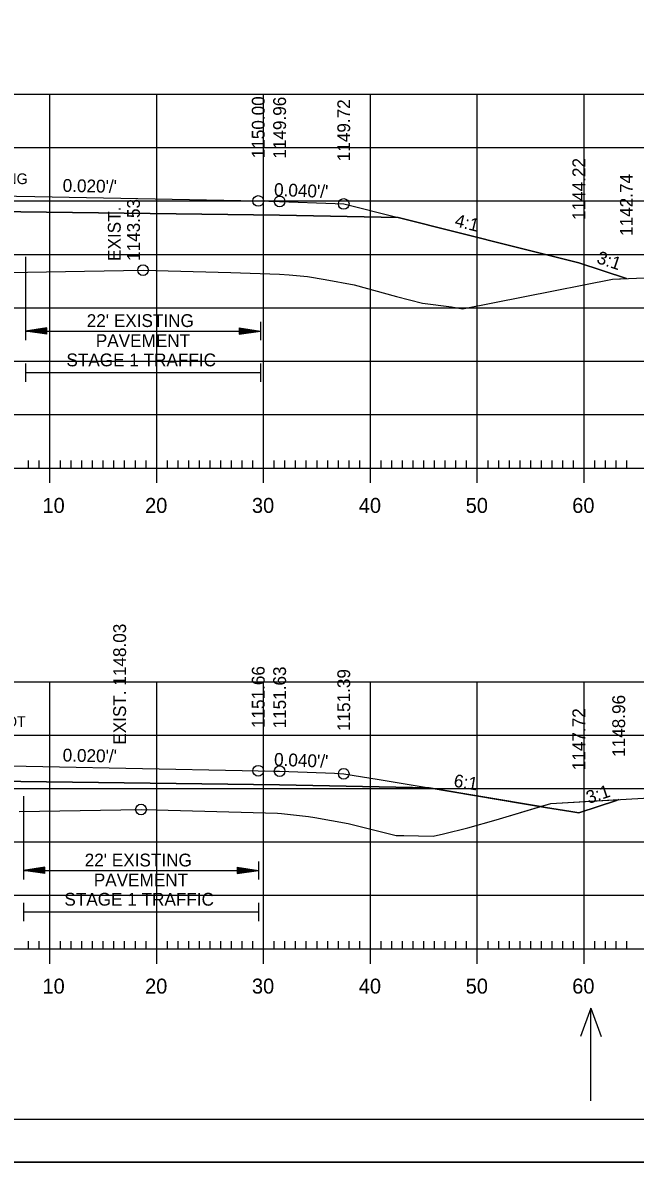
# Model space of a CAD drawing. Extents: x 1322838 to 1324533, y 339903 to 351025.
# Drawn here: x 1323711.2 to 1323768.5, y 341609.8 to 341716.5 of the extents above; entities that cross this region are included whole.
import ezdxf

# ---------------------------------------------------------------- set-up
doc = ezdxf.new("R2010")
doc.units = 0
for name, color, linetype in [('R_Alt Surface', 7, 'Continuous'), ('R_Axis', 7, 'Continuous'), ('R_Axis Annot', 7, 'Continuous'), ('R_Border', 7, 'Continuous'), ('R_Exist Surface', 7, 'Continuous'), ('R_Fin Surface', 7, 'Continuous'), ('R_Fin Surface Annot', 7, 'Continuous'), ('R_Grid', 7, 'Continuous'), ('R_No Plot', 7, 'Continuous'), ('R_Water Annot', 7, 'Continuous'), ('R_Xsect Elev', 7, 'Continuous')]:
    doc.layers.add(name, color=color, linetype=linetype)

msp = doc.modelspace()

# ---------------------------------------------------------------- linework, layer by layer
at = {"layer": 'R_Alt Surface'}
for points in [[(1323661.12, 341698.25), (1323672.22, 341698.48), (1323703.72, 341698.9), (1323735.22, 341698.48), (1323746.31, 341698.25)], [(1323661.12, 341644.92), (1323672.22, 341645.14), (1323703.72, 341645.56), (1323735.22, 341645.14), (1323749.21, 341644.86)]]:
    msp.add_lwpolyline(points, dxfattribs=at)
at = {"layer": 'R_Axis'}
for p, q in [((1323713.72, 341673.41), (1323713.72, 341676.21)), ((1323723.72, 341673.41), (1323723.72, 341676.21)), ((1323733.72, 341673.41), (1323733.72, 341676.21)), ((1323743.72, 341673.41), (1323743.72, 341676.21)), ((1323753.72, 341673.41), (1323753.72, 341676.21)), ((1323763.72, 341673.41), (1323763.72, 341676.21)), ((1323711.72, 341674.81), (1323711.72, 341675.51)), ((1323712.72, 341674.81), (1323712.72, 341675.51)), ((1323714.72, 341674.81), (1323714.72, 341675.51)), ((1323715.72, 341674.81), (1323715.72, 341675.51)), ((1323716.72, 341674.81), (1323716.72, 341675.51)), ((1323717.72, 341674.81), (1323717.72, 341675.51)), ((1323718.72, 341674.81), (1323718.72, 341675.51)), ((1323719.72, 341674.81), (1323719.72, 341675.51)), ((1323720.72, 341674.81), (1323720.72, 341675.51)), ((1323721.72, 341674.81), (1323721.72, 341675.51)), ((1323722.72, 341674.81), (1323722.72, 341675.51)), ((1323724.72, 341674.81), (1323724.72, 341675.51)), ((1323725.72, 341674.81), (1323725.72, 341675.51)), ((1323726.72, 341674.81), (1323726.72, 341675.51)), ((1323727.72, 341674.81), (1323727.72, 341675.51)), ((1323728.72, 341674.81), (1323728.72, 341675.51)), ((1323729.72, 341674.81), (1323729.72, 341675.51)), ((1323730.72, 341674.81), (1323730.72, 341675.51)), ((1323731.72, 341674.81), (1323731.72, 341675.51)), ((1323732.72, 341674.81), (1323732.72, 341675.51)), ((1323734.72, 341674.81), (1323734.72, 341675.51)), ((1323735.72, 341674.81), (1323735.72, 341675.51)), ((1323736.72, 341674.81), (1323736.72, 341675.51)), ((1323737.72, 341674.81), (1323737.72, 341675.51)), ((1323738.72, 341674.81), (1323738.72, 341675.51)), ((1323739.72, 341674.81), (1323739.72, 341675.51)), ((1323740.72, 341674.81), (1323740.72, 341675.51)), ((1323741.72, 341674.81), (1323741.72, 341675.51)), ((1323742.72, 341674.81), (1323742.72, 341675.51)), ((1323744.72, 341674.81), (1323744.72, 341675.51)), ((1323745.72, 341674.81), (1323745.72, 341675.51)), ((1323746.72, 341674.81), (1323746.72, 341675.51)), ((1323747.72, 341674.81), (1323747.72, 341675.51)), ((1323748.72, 341674.81), (1323748.72, 341675.51)), ((1323749.72, 341674.81), (1323749.72, 341675.51)), ((1323750.72, 341674.81), (1323750.72, 341675.51)), ((1323751.72, 341674.81), (1323751.72, 341675.51)), ((1323752.72, 341674.81), (1323752.72, 341675.51)), ((1323754.72, 341674.81), (1323754.72, 341675.51)), ((1323755.72, 341674.81), (1323755.72, 341675.51)), ((1323756.72, 341674.81), (1323756.72, 341675.51)), ((1323757.72, 341674.81), (1323757.72, 341675.51)), ((1323758.72, 341674.81), (1323758.72, 341675.51)), ((1323759.72, 341674.81), (1323759.72, 341675.51)), ((1323760.72, 341674.81), (1323760.72, 341675.51)), ((1323761.72, 341674.81), (1323761.72, 341675.51)), ((1323762.72, 341674.81), (1323762.72, 341675.51)), ((1323764.72, 341674.81), (1323764.72, 341675.51)), ((1323765.72, 341674.81), (1323765.72, 341675.51)), ((1323766.72, 341674.81), (1323766.72, 341675.51)), ((1323767.72, 341674.81), (1323767.72, 341675.51)), ((1323563.72, 341674.81), (1323843.72, 341674.81)), ((1323711.72, 341629.81), (1323711.72, 341630.51)), ((1323712.72, 341629.81), (1323712.72, 341630.51)), ((1323713.72, 341628.41), (1323713.72, 341631.21)), ((1323714.72, 341629.81), (1323714.72, 341630.51)), ((1323715.72, 341629.81), (1323715.72, 341630.51)), ((1323716.72, 341629.81), (1323716.72, 341630.51)), ((1323717.72, 341629.81), (1323717.72, 341630.51)), ((1323718.72, 341629.81), (1323718.72, 341630.51)), ((1323719.72, 341629.81), (1323719.72, 341630.51)), ((1323720.72, 341629.81), (1323720.72, 341630.51)), ((1323721.72, 341629.81), (1323721.72, 341630.51)), ((1323722.72, 341629.81), (1323722.72, 341630.51)), ((1323723.72, 341628.41), (1323723.72, 341631.21)), ((1323724.72, 341629.81), (1323724.72, 341630.51)), ((1323725.72, 341629.81), (1323725.72, 341630.51)), ((1323726.72, 341629.81), (1323726.72, 341630.51)), ((1323727.72, 341629.81), (1323727.72, 341630.51)), ((1323728.72, 341629.81), (1323728.72, 341630.51)), ((1323729.72, 341629.81), (1323729.72, 341630.51)), ((1323730.72, 341629.81), (1323730.72, 341630.51)), ((1323731.72, 341629.81), (1323731.72, 341630.51)), ((1323732.72, 341629.81), (1323732.72, 341630.51)), ((1323733.72, 341628.41), (1323733.72, 341631.21)), ((1323734.72, 341629.81), (1323734.72, 341630.51)), ((1323735.72, 341629.81), (1323735.72, 341630.51)), ((1323736.72, 341629.81), (1323736.72, 341630.51)), ((1323737.72, 341629.81), (1323737.72, 341630.51)), ((1323738.72, 341629.81), (1323738.72, 341630.51)), ((1323739.72, 341629.81), (1323739.72, 341630.51)), ((1323740.72, 341629.81), (1323740.72, 341630.51)), ((1323741.72, 341629.81), (1323741.72, 341630.51)), ((1323742.72, 341629.81), (1323742.72, 341630.51)), ((1323743.72, 341628.41), (1323743.72, 341631.21)), ((1323744.72, 341629.81), (1323744.72, 341630.51)), ((1323745.72, 341629.81), (1323745.72, 341630.51)), ((1323746.72, 341629.81), (1323746.72, 341630.51)), ((1323747.72, 341629.81), (1323747.72, 341630.51)), ((1323748.72, 341629.81), (1323748.72, 341630.51)), ((1323749.72, 341629.81), (1323749.72, 341630.51)), ((1323750.72, 341629.81), (1323750.72, 341630.51)), ((1323751.72, 341629.81), (1323751.72, 341630.51)), ((1323752.72, 341629.81), (1323752.72, 341630.51)), ((1323753.72, 341628.41), (1323753.72, 341631.21)), ((1323754.72, 341629.81), (1323754.72, 341630.51)), ((1323755.72, 341629.81), (1323755.72, 341630.51)), ((1323756.72, 341629.81), (1323756.72, 341630.51)), ((1323757.72, 341629.81), (1323757.72, 341630.51)), ((1323758.72, 341629.81), (1323758.72, 341630.51)), ((1323759.72, 341629.81), (1323759.72, 341630.51)), ((1323760.72, 341629.81), (1323760.72, 341630.51)), ((1323761.72, 341629.81), (1323761.72, 341630.51)), ((1323762.72, 341629.81), (1323762.72, 341630.51)), ((1323763.72, 341628.41), (1323763.72, 341631.21)), ((1323764.72, 341629.81), (1323764.72, 341630.51)), ((1323765.72, 341629.81), (1323765.72, 341630.51)), ((1323766.72, 341629.81), (1323766.72, 341630.51)), ((1323767.72, 341629.81), (1323767.72, 341630.51)), ((1323563.72, 341629.81), (1323843.72, 341629.81))]:
    msp.add_line(p, q, dxfattribs=at)
at = {"layer": 'R_Axis Annot'}
for p, q in [((1323711.44, 341688.49), (1323711.44, 341686.78)), ((1323713.44, 341687.93), (1323711.44, 341687.63)), ((1323713.44, 341687.33), (1323713.44, 341687.93)), ((1323731.44, 341687.93), (1323733.44, 341687.63)), ((1323731.44, 341687.93), (1323731.44, 341687.33)), ((1323733.44, 341688.49), (1323733.44, 341686.78)), ((1323713.44, 341687.33), (1323711.44, 341687.63)), ((1323711.44, 341687.63), (1323733.44, 341687.63)), ((1323713.44, 341687.88), (1323711.78, 341687.63)), ((1323713.44, 341687.38), (1323711.78, 341687.63)), ((1323713.44, 341687.83), (1323712.12, 341687.63)), ((1323713.44, 341687.43), (1323712.12, 341687.63)), ((1323713.44, 341687.78), (1323712.45, 341687.63)), ((1323713.44, 341687.48), (1323712.45, 341687.63)), ((1323713.44, 341687.73), (1323712.79, 341687.63)), ((1323713.44, 341687.54), (1323712.79, 341687.63)), ((1323713.44, 341687.68), (1323713.13, 341687.63)), ((1323713.44, 341687.59), (1323713.13, 341687.63)), ((1323731.44, 341687.88), (1323733.11, 341687.63)), ((1323731.44, 341687.83), (1323732.76, 341687.63)), ((1323731.44, 341687.78), (1323732.43, 341687.63)), ((1323731.44, 341687.73), (1323732.09, 341687.63)), ((1323731.44, 341687.68), (1323731.76, 341687.63)), ((1323731.44, 341687.33), (1323733.44, 341687.63)), ((1323731.44, 341687.53), (1323732.09, 341687.63)), ((1323731.44, 341687.43), (1323732.76, 341687.63)), ((1323731.44, 341687.38), (1323733.11, 341687.63)), ((1323731.44, 341687.48), (1323732.43, 341687.63)), ((1323731.44, 341687.59), (1323731.76, 341687.63)), ((1323711.44, 341684.6), (1323711.44, 341682.89)), ((1323711.44, 341683.74), (1323733.44, 341683.74)), ((1323733.44, 341684.6), (1323733.44, 341682.89)), ((1323711.25, 341637.99), (1323711.25, 341636.29)), ((1323733.25, 341637.99), (1323733.25, 341636.29)), ((1323713.25, 341637.44), (1323711.25, 341637.14)), ((1323713.25, 341636.84), (1323711.25, 341637.14)), ((1323711.25, 341637.14), (1323733.25, 341637.14)), ((1323713.25, 341637.39), (1323711.58, 341637.14)), ((1323713.25, 341636.89), (1323711.58, 341637.14)), ((1323713.25, 341637.34), (1323711.93, 341637.14)), ((1323713.25, 341636.94), (1323711.93, 341637.14)), ((1323713.25, 341637.29), (1323712.26, 341637.14)), ((1323713.25, 341636.99), (1323712.26, 341637.14)), ((1323713.25, 341637.24), (1323712.6, 341637.14)), ((1323713.25, 341637.04), (1323712.6, 341637.14)), ((1323713.25, 341637.19), (1323712.93, 341637.14)), ((1323713.25, 341637.09), (1323712.93, 341637.14)), ((1323713.25, 341636.84), (1323713.25, 341637.44)), ((1323731.25, 341637.44), (1323733.25, 341637.14)), ((1323731.25, 341637.44), (1323731.25, 341636.84)), ((1323731.25, 341637.39), (1323732.92, 341637.14)), ((1323731.25, 341637.34), (1323732.57, 341637.14)), ((1323731.25, 341637.29), (1323732.24, 341637.14)), ((1323731.25, 341637.24), (1323731.9, 341637.14)), ((1323731.25, 341637.19), (1323731.57, 341637.14)), ((1323731.25, 341636.84), (1323733.25, 341637.14)), ((1323731.25, 341637.04), (1323731.9, 341637.14)), ((1323731.25, 341636.94), (1323732.57, 341637.14)), ((1323731.25, 341636.89), (1323732.92, 341637.14)), ((1323731.25, 341636.99), (1323732.24, 341637.14)), ((1323731.25, 341637.09), (1323731.57, 341637.14)), ((1323711.25, 341634.1), (1323711.25, 341632.4)), ((1323733.25, 341634.1), (1323733.25, 341632.4)), ((1323711.25, 341633.25), (1323733.25, 341633.25))]:
    msp.add_line(p, q, dxfattribs=at)
at = {"layer": 'R_Border'}
msp.add_line((1323861.9, 341613.81), (1323545.72, 341613.81), dxfattribs=at)
at = {"layer": 'R_Exist Surface'}
for points in [[(1323709.84, 341693.11), (1323716.97, 341693.24), (1323722.44, 341693.33), (1323730.65, 341693.11), (1323735.2, 341692.97), (1323736.11, 341692.89), (1323737.83, 341692.73), (1323739.48, 341692.46), (1323742.19, 341691.97), (1323746.16, 341690.88), (1323748.59, 341690.23), (1323751.31, 341689.89), (1323752.34, 341689.7), (1323758.18, 341690.86), (1323766.36, 341692.49), (1323775.39, 341692.85)], [(1323710.86, 341642.66), (1323722.25, 341642.84), (1323723.68, 341642.8), (1323735.02, 341642.5), (1323735.39, 341642.46), (1323737.92, 341642.18), (1323738.51, 341642.09), (1323741.62, 341641.54), (1323742.51, 341641.32), (1323746.12, 341640.41), (1323746.84, 341640.42), (1323749.58, 341640.36), (1323750.56, 341640.56), (1323752.84, 341641.13), (1323755.49, 341641.89), (1323760.6, 341643.41), (1323776.32, 341644.3)]]:
    msp.add_lwpolyline(points, dxfattribs=at)
at = {"layer": 'R_Fin Surface'}
for points in [[(1323617.25, 341685.04), (1323633.99, 341690.62), (1323644.22, 341694.03), (1323654.8, 341696.67), (1323661.12, 341698.25), (1323664.73, 341699.16), (1323666.22, 341699.53), (1323672.22, 341699.77), (1323674.22, 341699.81), (1323703.72, 341700.4), (1323712.33, 341700.23), (1323733.22, 341699.81), (1323735.22, 341699.77), (1323740.41, 341699.56), (1323741.22, 341699.53), (1323746.31, 341698.25), (1323757.36, 341695.49), (1323763.22, 341694.03), (1323767.67, 341692.54)], [(1323660.28, 341644.71), (1323661.12, 341644.92), (1323665.41, 341645.99), (1323666.22, 341646.19), (1323669.75, 341646.33), (1323672.22, 341646.43), (1323674.22, 341646.47), (1323690.81, 341646.8), (1323700.04, 341646.99), (1323703.72, 341647.06), (1323731.71, 341646.5), (1323733.22, 341646.47), (1323734.64, 341646.44), (1323735.22, 341646.43), (1323736.08, 341646.4), (1323740.36, 341646.23), (1323741.22, 341646.19), (1323744.53, 341645.64), (1323749.21, 341644.86), (1323760.1, 341643.04), (1323762.48, 341642.65), (1323763.22, 341642.52), (1323766.75, 341643.7), (1323766.95, 341643.77)]]:
    msp.add_lwpolyline(points, dxfattribs=at)
at = {"layer": 'R_Grid'}
for p, q in [((1323563.72, 341709.81), (1323843.72, 341709.81)), ((1323713.72, 341674.81), (1323713.72, 341709.81)), ((1323723.72, 341674.81), (1323723.72, 341709.81)), ((1323733.72, 341674.81), (1323733.72, 341709.81)), ((1323743.72, 341674.81), (1323743.72, 341709.81)), ((1323753.72, 341674.81), (1323753.72, 341709.81)), ((1323763.72, 341674.81), (1323763.72, 341709.81)), ((1323563.72, 341704.81), (1323843.72, 341704.81)), ((1323563.72, 341699.81), (1323843.72, 341699.81)), ((1323563.72, 341694.81), (1323843.72, 341694.81)), ((1323563.72, 341689.81), (1323843.72, 341689.81)), ((1323563.72, 341684.81), (1323843.72, 341684.81)), ((1323563.72, 341679.81), (1323843.72, 341679.81)), ((1323563.72, 341674.81), (1323843.72, 341674.81)), ((1323563.72, 341654.81), (1323843.72, 341654.81)), ((1323713.72, 341629.81), (1323713.72, 341654.81)), ((1323723.72, 341629.81), (1323723.72, 341654.81)), ((1323733.72, 341629.81), (1323733.72, 341654.81)), ((1323743.72, 341629.81), (1323743.72, 341654.81)), ((1323753.72, 341629.81), (1323753.72, 341654.81)), ((1323763.72, 341629.81), (1323763.72, 341654.81)), ((1323563.72, 341649.81), (1323843.72, 341649.81)), ((1323563.72, 341644.81), (1323843.72, 341644.81)), ((1323563.72, 341639.81), (1323843.72, 341639.81)), ((1323563.72, 341634.81), (1323843.72, 341634.81)), ((1323563.72, 341629.81), (1323843.72, 341629.81))]:
    msp.add_line(p, q, dxfattribs=at)
at = {"layer": 'R_No Plot'}
for p, q in [((1323711.44, 341694.59), (1323711.44, 341688.49)), ((1323711.25, 341644.1), (1323711.25, 341637.99)), ((1323533.31, 341609.83), (1323866.65, 341609.83))]:
    msp.add_line(p, q, dxfattribs=at)
for points in [[(1323533.31, 341823.16), (1323866.65, 341823.16), (1323866.65, 341609.82), (1323533.31, 341609.82)], [(1323779.64, 341819.27), (1323799.26, 341819.27), (1323799.26, 341809.39), (1323815.37, 341809.39), (1323838.57, 341809.39), (1323838.57, 341776.72), (1323861.77, 341776.72), (1323861.9, 341613.81), (1323545.72, 341613.81), (1323545.72, 341819.27)], [(1323759.63, 341643.12), (1323760.6, 341643.41), (1323766.95, 341643.77), (1323766.75, 341643.7), (1323763.22, 341642.52), (1323762.48, 341642.65), (1323760.1, 341643.04)]]:
    msp.add_lwpolyline(points, close=True, dxfattribs=at)
for points in [[(1323709.84, 341693.11), (1323716.97, 341693.24), (1323722.44, 341693.33), (1323730.65, 341693.11), (1323735.2, 341692.97), (1323736.11, 341692.89), (1323737.83, 341692.73), (1323739.48, 341692.46), (1323742.19, 341691.97), (1323746.16, 341690.88), (1323748.59, 341690.23), (1323751.31, 341689.89), (1323752.34, 341689.7), (1323758.18, 341690.86), (1323766.36, 341692.49), (1323767.67, 341692.54), (1323763.22, 341694.03), (1323757.36, 341695.49), (1323746.31, 341698.25), (1323735.22, 341698.48), (1323703.72, 341698.9)], [(1323710.86, 341642.66), (1323722.25, 341642.84), (1323723.68, 341642.8), (1323735.02, 341642.5), (1323735.39, 341642.46), (1323737.92, 341642.18), (1323738.51, 341642.09), (1323741.62, 341641.54), (1323742.51, 341641.32), (1323746.12, 341640.41), (1323746.84, 341640.42), (1323749.58, 341640.36), (1323750.56, 341640.56), (1323752.84, 341641.13), (1323755.49, 341641.89), (1323759.63, 341643.12), (1323749.21, 341644.86), (1323735.22, 341645.14), (1323703.72, 341645.56)]]:
    msp.add_lwpolyline(points, dxfattribs=at)
for centre in [(1323733.22, 341699.81), (1323733.22, 341699.81), (1323735.22, 341699.77), (1323735.22, 341699.77), (1323741.22, 341699.53), (1323741.22, 341699.53), (1323722.44, 341693.33), (1323733.22, 341646.47), (1323733.22, 341646.47), (1323735.22, 341646.43), (1323735.22, 341646.43), (1323741.22, 341646.19), (1323741.22, 341646.19), (1323722.25, 341642.84)]:
    msp.add_circle(centre, 0.5, dxfattribs=at)
at = {"layer": 'R_Water Annot'}
for p, q in [((1323764.33, 341624.26), (1323763.36, 341621.6)), ((1323764.33, 341615.57), (1323764.33, 341624.26)), ((1323764.33, 341624.26), (1323765.3, 341621.6))]:
    msp.add_line(p, q, dxfattribs=at)

# ---------------------------------------------------------------- texts
at = {"layer": 'R_Axis Annot'}
for s, height, p in [("22' EXISTING ", 1.2, (1323717.17, 341688.01)), ('PAVEMENT', 1.2, (1323718.02, 341686.14)), ('STAGE 1 TRAFFIC', 1.2, (1323715.27, 341684.33)), ('10', 1.4, (1323713.03, 341670.61)), ('20', 1.4, (1323722.63, 341670.61)), ('30', 1.4, (1323732.63, 341670.61)), ('40', 1.4, (1323742.63, 341670.61)), ('50', 1.4, (1323752.63, 341670.61)), ('60', 1.4, (1323762.6, 341670.61)), ("22' EXISTING ", 1.2, (1323716.98, 341637.51)), ('PAVEMENT', 1.2, (1323717.83, 341635.65)), ('STAGE 1 TRAFFIC', 1.2, (1323715.08, 341633.84)), ('10', 1.4, (1323713.03, 341625.61)), ('20', 1.4, (1323722.63, 341625.61)), ('30', 1.4, (1323732.63, 341625.61)), ('40', 1.4, (1323742.63, 341625.61)), ('50', 1.4, (1323752.63, 341625.61)), ('60', 1.4, (1323762.6, 341625.61))]:
    msp.add_text(s, height=height, dxfattribs=at).set_placement(p)
at = {"layer": 'R_Fin Surface Annot'}
for s, rotation, p in [('1150.00', 90, (1323733.82, 341703.81)), ('1149.96', 90, (1323735.82, 341703.77)), ('1149.72', 90, (1323741.82, 341703.53)), ('1144.22', 90, (1323763.82, 341698.03)), ("0.020'/'", 358.8542, (1323714.91, 341700.67)), ('1142.74', 90, (1323768.27, 341696.54)), ("0.040'/'", 357.7093, (1323734.68, 341700.29)), ('4:1', 345.9638, (1323751.53, 341697.46)), ('3:1', 341.5575, (1323764.81, 341694.02)), ('1151.66', 90, (1323733.82, 341650.47)), ('1151.63', 90, (1323735.82, 341650.43)), ('1151.39', 90, (1323741.82, 341650.19)), ('1148.96', 90, (1323767.55, 341647.77)), ('1147.72', 90, (1323763.82, 341646.52)), ("0.020'/'", 358.8542, (1323714.91, 341647.34)), ("0.040'/'", 357.7094, (1323734.68, 341646.95)), ('6:1', 350.5369, (1323751.45, 341644.99)), ('3:1', 18.4349, (1323764.14, 341643.36))]:
    msp.add_text(s, height=1.2, rotation=rotation, dxfattribs=at).set_placement(p)
at = {"layer": 'R_No Plot'}
for s, p in [('PLATING', (1323705.93, 341701.39)), ('2:1 MOT', (1323706.27, 341650.58))]:
    msp.add_text(s, height=1, dxfattribs=at).set_placement(p)
at = {"layer": 'R_Xsect Elev'}
for s, p in [('1143.53', (1323722.15, 341694.2)), ('EXIST. ', (1323720.35, 341694.2)), ('EXIST. 1148.03', (1323720.85, 341648.91))]:
    msp.add_text(s, height=1.2, rotation=90, dxfattribs=at).set_placement(p)

doc.saveas('drawing.dxf')
